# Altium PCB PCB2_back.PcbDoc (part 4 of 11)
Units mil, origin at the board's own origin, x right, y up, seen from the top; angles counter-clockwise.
Board outline 6299 x 3937 mil, 4 copper layers (TopLayer, GROUND, VCC, BottomLayer); 290 components, 470 nets, 2252 pads, 825 vias.
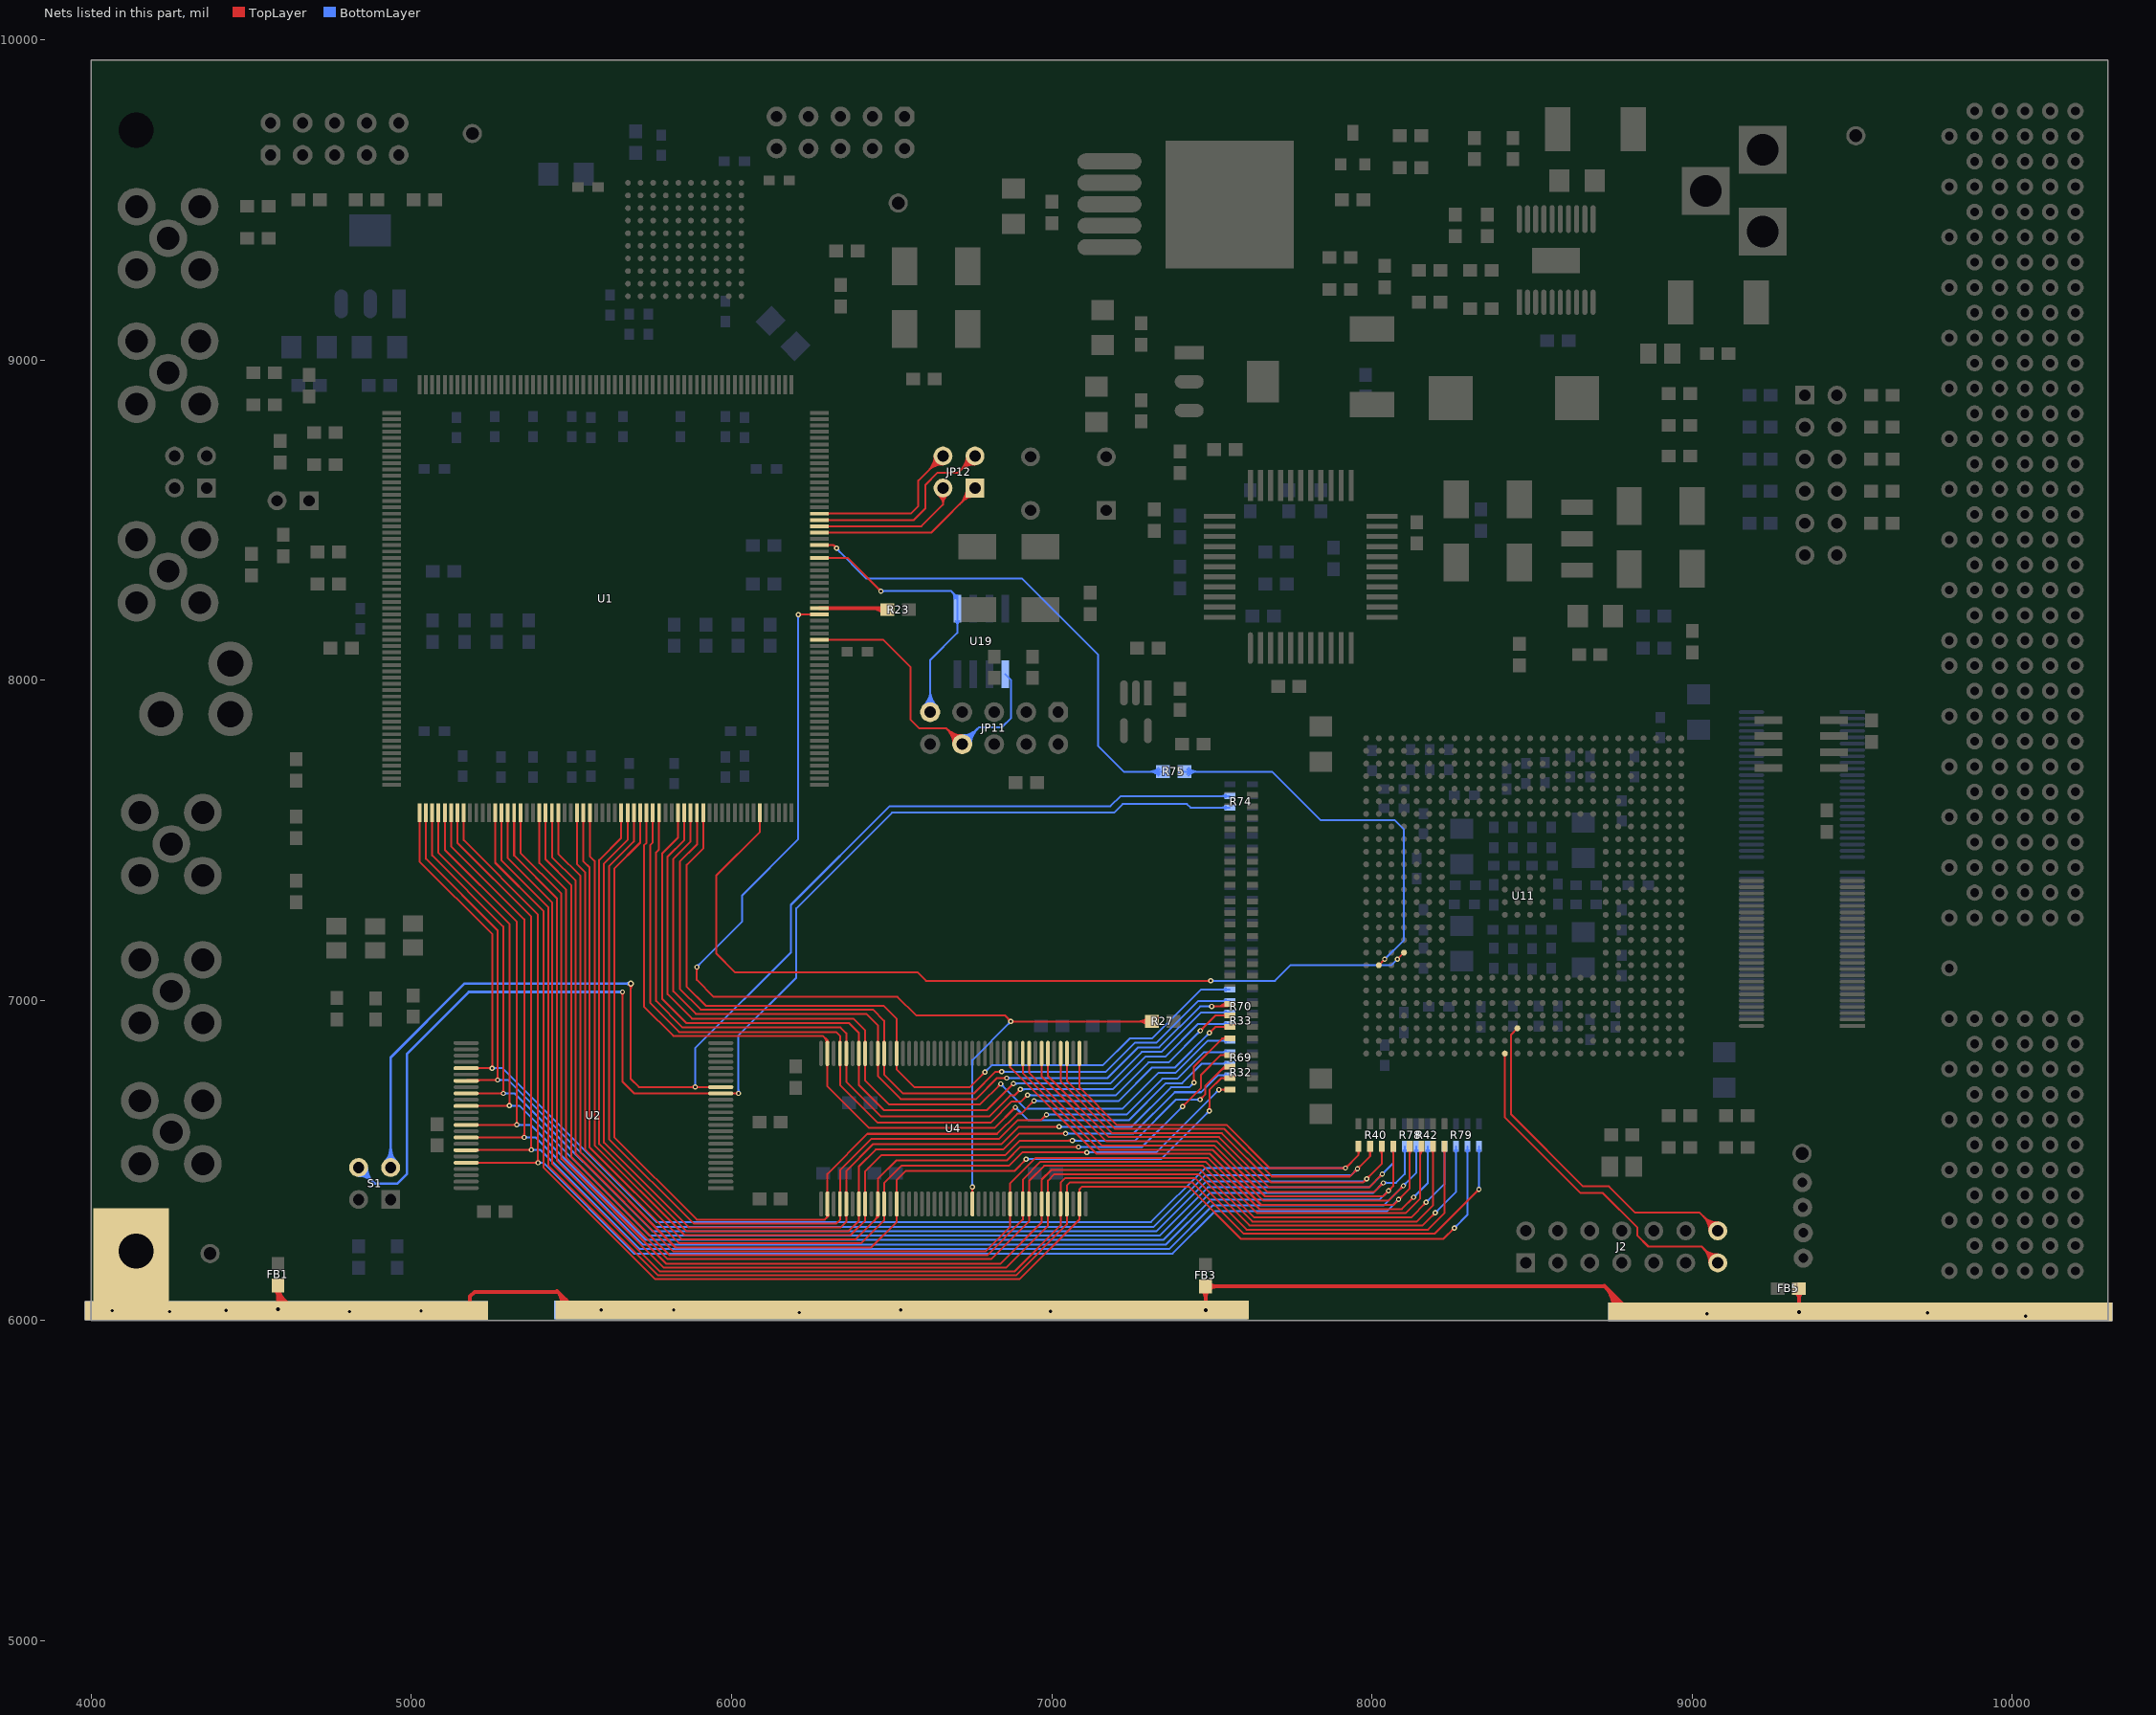
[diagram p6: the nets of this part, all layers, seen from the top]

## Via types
v1: diameter 16, hole 8, TopLayer to BottomLayer, 408 vias
v2: diameter 20, hole 10, TopLayer to BottomLayer, 221 vias
v3: diameter 24, hole 12, TopLayer to BottomLayer, 194 vias
v4: diameter 56.69, hole 56.69, TopLayer to BottomLayer, 2 vias

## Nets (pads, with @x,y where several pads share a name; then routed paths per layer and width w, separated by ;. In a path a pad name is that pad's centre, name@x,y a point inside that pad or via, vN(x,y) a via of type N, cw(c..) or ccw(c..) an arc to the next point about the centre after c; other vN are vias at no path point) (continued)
EA21: R74.7 S1.3 U2.17 | length 4303.4
  TopLayer w6: v2@5680.05,7047.05 cw(c5668.1,7035.1) 5685,7035.1 cw(c5701.9,7035.1) v2@5689.95,7047.05 ; v2(5685,7052) 5685,6754 5710.04,6728.96 U2.17@5966,6728.96 ; v1@5882.5,6725.42 ccw(c5873.97,6716.89) 5873.97,6728.96 ccw(c5873.97,6741.03) v1@5882.5,6732.5 ; v1@5889.58,6725.42 cw(c5898.11,6716.89) 5898.11,6728.96 cw(c5898.11,6741.03) v1@5889.58,6732.5 ; U2.17@5930.48,6726.91 ccw(c5925.52,6721.95) 5925.52,6728.96 ccw(c5925.52,6735.97) U2.17@5930.48,6731.01
  BottomLayer w6: v1@5882.5,6732.5 ccw(c5873.97,6741.03) 5886.04,6741.03 ccw(c5898.11,6741.03) v1@5889.58,6732.5 ; v1(5886.04,6728.96) 5886.04,6851.04 6185,7150 6185,7298 6493,7606 7183,7606 7215,7638 R74.7@7555.84,7638 ; R74.7@7543.1,7633.76 ccw(c7532.86,7623.51) 7532.86,7638 ccw(c7532.86,7652.49) R74.7@7543.1,7642.24
  BottomLayer w8: S1.3@4916.95,6496.05 ccw(c4873.37,6539.63) 4935,6539.63 ccw(c4996.63,6539.63) S1.3@4953.05,6496.05 ; S1.3@4922.61,6490.39 ccw(c4892.68,6520.32) 4935,6520.32 ccw(c4977.32,6520.32) S1.3@4947.39,6490.39 ; S1.3@4923,6490 S1.3@4935,6478 4935,6822 5165,7052 v2(5685,7052) ; v2@5680.76,7047.76 ccw(c5670.51,7037.51) 5670.51,7052 ccw(c5670.51,7066.49) v2@5680.76,7056.24
EA22: R74.6 S1.4 U2.16 | length 4396.5
  TopLayer w6: v1@5655.46,7022.46 cw(c5646.93,7013.93) 5659,7013.93 cw(c5671.07,7013.93) v1@5662.54,7022.46 ; v1(5659,7026) 5659,6746.27 5696,6709.27 ; 5695,6709 5966,6709.23 v1(6021.27,6709.27) ; 5925.34,6709.19 ccw(c5925.33,6716.46) U2.16@5930.48,6711.33 ; 5925.7,6709.19 cw(c5925.71,6702.44) U2.16@5930.48,6707.22 ; U2.16@6001.52,6707.22 cw(c6006.44,6702.31) 6006.43,6709.26 ; U2.16@6001.52,6711.33 ccw(c6006.52,6716.34) 6006.52,6709.26 ; v1@6017.74,6705.74 ccw(c6009.21,6697.19) 6009.2,6709.26 ccw(c6009.19,6721.34) v1@6017.74,6712.81
  BottomLayer w6: v1@6017.74,6712.81 ccw(c6009.2,6721.35) 6021.28,6721.35 ccw(c6033.35,6721.35) v1@6024.81,6712.81 ; v1(6021.27,6709.27) 6021.27,6890.27 6202,7071 6202,7287 6501,7586 7194,7586 7221,7613 7422,7613 7433,7602 R74.6@7555.84,7602 ; R74.6@7543.1,7597.76 ccw(c7532.86,7587.51) 7532.86,7602 ccw(c7532.86,7616.49) R74.6@7543.1,7606.24
  BottomLayer w8: S1.4@4835,6452.47 cw(c4835,6390.84) 4878.58,6434.42 cw(c4922.16,6478) S1.4@4860.53,6478 ; S1.4@4835,6460.47 cw(c4835,6418.16) 4864.92,6448.08 cw(c4894.84,6478) S1.4@4852.53,6478 ; S1.4@4835,6478 4885,6428 4956,6428 4986,6458 4986,6833 5179,7026 v1(5659,7026) ; v1@5656.17,7023.17 ccw(c5649.34,7016.34) 5649.34,7026 ccw(c5649.34,7035.66) v1@5656.17,7028.83
ECLKIN: R75.2 U11.H25 | length 1321.4
  TopLayer w6: U11.H25@8021.12,7109.59 v1(8039.53,7128)
  BottomLayer w6: R75.2@7413.46,7714 7688,7714 7839,7563 8070,7563 8100,7533 8100,7188.47 v1(8039.53,7128) ; R75.2@7422.99,7706.44 cw(c7441.23,7688.2) 7441.23,7714 cw(c7441.23,7739.8) R75.2@7422.99,7721.56 ; R75.2@7427.23,7702.2 cw(c7455.71,7673.72) 7455.71,7714 cw(c7455.71,7754.28) R75.2@7427.23,7725.8
ECLKOUT1: R27.2 U1.28 U4.68 | length 3730.1
  TopLayer w6: v1@5887.46,7100.46 cw(c5878.93,7091.93) 5891,7091.93 cw(c5903.07,7091.93) v1@5894.54,7100.46 ; v1(5891,7104) 5891,7064 5944,7011 6518,7011 6576,6953 6853,6953 v1(6872,6934) R27.2@7312.54,6934 ; v1(6208,8204.79) U1.28@6274.31,8204.79 ; v1@6211.54,8201.25 cw(c6220.07,8192.72) 6220.07,8204.79 cw(c6220.07,8216.86) v1@6211.54,8208.32 ; U1.28@6248.63,8202.73 ccw(c6243.67,8197.77) 6243.67,8204.79 ccw(c6243.67,8211.8) U1.28@6248.63,8206.84 ; v1@6748.13,6413.13 cw(c6739.6,6404.6) 6751.67,6404.6 cw(c6763.74,6404.6) v1@6755.21,6413.13 ; U4.68@6749.62,6399.52 ccw(c6744.66,6404.48) 6751.67,6404.48 ccw(c6758.68,6404.48) U4.68@6753.72,6399.52 ; U4.68@6751.67,6364 v1(6751.67,6416.67) ; v1@6867,6934 ccw(c6854.93,6934) 6863.46,6942.54 ccw(c6872,6951.07) v1@6872,6939 ; v1@6875.54,6930.46 cw(c6884.07,6921.93) 6884.07,6934 cw(c6884.07,6946.07) v1@6875.54,6937.54 ; R27.2@7298.77,6922.2 ccw(c7270.29,6893.72) 7270.29,6934 ccw(c7270.29,6974.28) R27.2@7298.77,6945.8 ; R27.2@7303.01,6926.44 ccw(c7284.77,6908.2) 7284.77,6934 ccw(c7284.77,6959.8) R27.2@7303.01,6941.56
  BottomLayer w6: v1(5891,7104) 6033,7246 6033,7328 6208,7503 v1(6208,8204.79) ; v1@5891,7109 ccw(c5891,7121.07) 5899.54,7112.54 ccw(c5908.07,7104) v1@5896,7104 ; v1@6204.46,8201.25 cw(c6195.93,8192.72) 6208,8192.72 cw(c6220.07,8192.72) v1@6211.54,8201.25 ; v1@6748.13,6420.21 ccw(c6739.6,6428.74) 6751.67,6428.74 ccw(c6763.74,6428.74) v1@6755.21,6420.21 ; v1(6751.67,6416.67) 6751.67,6813.67 v1(6872,6934) ; v1@6867,6934 cw(c6854.93,6934) 6863.46,6925.46 cw(c6872,6916.93) v1@6872,6929
ECLKOUT2: U1.235 U11.J23 | length 2764.6
  TopLayer w6: U1.235@6086.23,7560.02 cw(c6081.27,7555.06) 6088.28,7555.06 cw(c6095.3,7555.06) U1.235@6090.34,7560.02 ; U1.235@6088.28,7585.69 6088.28,7526.28 5952,7390 5952,7146 6010,7088 6580,7088 6607,7061 v1(7496,7061) ; v1@7492.46,7057.46 ccw(c7483.93,7048.93) 7483.93,7061 ccw(c7483.93,7073.07) v1@7492.46,7064.54 ; v1(8078.9,7128) U11.J23@8099.86,7148.96
  BottomLayer w6: v1(7496,7061) 7697,7061 7746,7110 8060.9,7110 v1(8078.9,7128) ; v1@7499.54,7057.46 cw(c7508.07,7048.93) 7508.07,7061 cw(c7508.07,7073.07) v1@7499.54,7064.54
ED00: R40.5 U1.181 U2.29 U4.2 | length 5201.9
  TopLayer w6: U1.181@5023.24,7560.02 cw(c5018.28,7555.06) 5025.29,7555.06 cw(c5032.31,7555.06) U1.181@5027.35,7560.02 ; U1.181@5025.29,7585.69 5025.29,7433.71 5252,7207 v1(5252,6788) U2.29@5170.72,6788.02 ; U2.29@5206.24,6785.96 cw(c5211.19,6781.01) 5211.19,6788.01 cw(c5211.22,6795.04) U2.29@5206.24,6790.07 ; v1@5248.46,6784.47 ccw(c5239.93,6775.93) 5239.93,6788 ccw(c5239.93,6800.07) 5248.47,6791.54 ccw(c5239.93,6800.07) 5252,6800.07 ccw(c5264.07,6800.07) v1@5255.54,6791.54 ; U4.2@7084.26,6798.48 cw(c7079.3,6793.52) 7086.32,6793.52 cw(c7093.33,6793.52) U4.2@7088.37,6798.48 ; U4.2@7086.31,6834 7086.31,6727.69 7204,6610 7547,6610 7681,6476 v1(7917,6476) 7958,6517 R40.5@7958,6543.84 ; v1@7913.46,6472.46 ccw(c7904.93,6463.93) 7904.93,6476 ccw(c7904.93,6488.07) v1@7913.46,6479.54 ; v1@7917,6481 ccw(c7917,6493.07) 7925.54,6484.54 ccw(c7934.07,6476) v1@7922,6476 ; R40.5@7953.76,6531.1 cw(c7943.51,6520.86) 7958,6520.86 cw(c7972.49,6520.86) R40.5@7962.24,6531.1
  BottomLayer w6: v1(5252,6788) 5284.98,6788.02 5765,6308 7310,6308 7478,6476 v1(7917,6476) ; v1@5255.54,6784.47 cw(c5264.08,6775.93) 5264.07,6788.01 cw(c5264.07,6800.08) v1@5255.53,6791.54 ; v1@7913.46,6472.46 ccw(c7904.93,6463.93) 7904.93,6476 ccw(c7904.93,6488.07) v1@7913.46,6479.54
ED01: R40.6 U1.182 U2.31 U4.4 | length 5358.9
  TopLayer w6: U1.182@5042.92,7560.02 cw(c5037.96,7555.06) 5044.98,7555.06 cw(c5051.99,7555.06) U1.182@5047.03,7560.02 ; U1.182@5044.98,7585.69 5044.98,7442.02 5269,7218 v1(5269,6751) U2.31@5173.08,6751 ; U2.31@5170.72,6748.65 U2.31@5173.08,6748.65 ; U2.31@5206.24,6746.59 cw(c5216.89,6735.94) 5216.89,6751 ; v1@5265.46,6747.46 ccw(c5256.93,6738.93) 5256.93,6751 ccw(c5256.93,6763.07) 5265.46,6754.54 ccw(c5256.93,6763.07) 5269,6763.07 ccw(c5281.07,6763.07) v1@5272.54,6754.54 ; U4.4@7044.89,6798.48 cw(c7039.93,6793.52) 7046.95,6793.52 cw(c7053.96,6793.52) U4.4@7049,6798.48 ; U4.4@7046.94,6834 7046.94,6749.06 7198,6598 7539,6598 7687,6450 7931,6450 7994,6513 R40.6@7994,6543.84 ; v1@7949.5,6473.5 cw(c7937.43,6473.5) 7945.97,6464.97 cw(c7954.5,6456.43) v1@7954.5,6468.5 ; v1@7954.5,6478.5 ccw(c7954.5,6490.57) 7963.04,6482.04 ccw(c7971.57,6473.5) v1@7959.5,6473.5 ; R40.6@7989.76,6531.1 cw(c7979.51,6520.86) 7994,6520.86 cw(c8008.49,6520.86) R40.6@7998.24,6531.1
  BottomLayer w6: v1(5269,6751) 5303,6751 5761,6293 7318,6293 7478,6453 7934,6453 v1(7954.5,6473.5) ; v1@5272.54,6747.46 cw(c5281.07,6738.93) 5281.07,6751 cw(c5281.07,6763.07) v1@5272.54,6754.54 ; v1@7949.5,6473.5 cw(c7937.43,6473.5) 7945.97,6464.97 cw(c7954.5,6456.43) v1@7954.5,6468.5
ED02: R40.7 U1.183 U2.33 U4.5 | length 5494.4
  TopLayer w6: U1.183@5062.61,7560.02 cw(c5057.65,7555.06) 5064.66,7555.06 cw(c5071.68,7555.06) U1.183@5066.72,7560.02 ; U1.183@5064.66,7585.69 5064.66,7452.34 5286.73,7230.27 v1(5286.73,6709.27) U2.33@5170.72,6709.27 ; U2.33@5206.24,6707.22 cw(c5211.2,6702.26) 5211.2,6709.28 cw(c5211.2,6716.29) U2.33@5206.24,6711.33 ; v1@5283.19,6705.74 ccw(c5274.65,6697.2) 5274.65,6709.28 ccw(c5274.65,6721.35) 5283.19,6712.81 ccw(c5274.65,6721.35) 5286.73,6721.35 ccw(c5298.8,6721.35) v1@5290.26,6712.81 ; U4.5@7025.21,6798.48 cw(c7020.25,6793.52) 7027.26,6793.52 cw(c7034.27,6793.52) U4.5@7029.31,6798.48 ; U4.5@7027.26,6834 7027.26,6746.74 7188.95,6585.05 7530.95,6585.05 7684,6432 7973,6432 8030,6489 R40.7@8030,6543.84 ; v1@7979,6443 cw(c7966.93,6443) 7975.46,6434.46 cw(c7984,6425.93) v1@7984,6438 ; v1@7984,6448 ccw(c7984,6460.07) 7992.54,6451.54 ccw(c8001.07,6443) v1@7989,6443 ; R40.7@8025.76,6531.1 cw(c8015.51,6520.86) 8030,6520.86 cw(c8044.49,6520.86) R40.7@8034.24,6531.1
  BottomLayer w6: v1(5286.73,6709.27) 5321.73,6709.27 5752,6279 7327,6279 7483,6435 7976,6435 ; v1@5290.26,6705.74 cw(c5298.8,6697.2) 5298.8,6709.28 cw(c5298.8,6721.35) v1@5290.26,6712.81 ; v1@7979.01,6442.77 cw(c7968.72,6442.28) 7976,6435 ; v1@7983.77,6438.01 ccw(c7983.28,6427.72) 7976,6435 ; v1(7984,6443) 7976,6435
ED03: R78.8 U1.184 U2.35 U4.7 | length 5659.6
  TopLayer w6: U1.184@5082.29,7560.02 cw(c5077.33,7555.06) 5084.35,7555.06 cw(c5091.36,7555.06) U1.184@5086.4,7560.02 ; U1.184@5084.35,7585.69 5084.35,7460.65 5306,7239 v1(5306,6671) 5171.82,6671 U2.35@5170.72,6669.9 ; U2.35@5206.24,6667.85 cw(c5213.85,6660.25) 5213.85,6671 ; v1@5302.46,6667.46 ccw(c5293.93,6658.93) 5293.93,6671 ccw(c5293.93,6683.07) 5302.46,6674.54 ccw(c5293.93,6683.07) 5306,6683.07 ccw(c5318.07,6683.07) v1@5309.54,6674.54 ; U4.7@6985.84,6798.48 cw(c6980.88,6793.52) 6987.89,6793.52 cw(c6994.9,6793.52) U4.7@6989.94,6798.48 ; U4.7@6987.89,6834 6987.89,6763.11 7178.14,6572.86 7522.14,6572.86 7679,6416 7991,6416 v1(8032,6457) ; v1@8027,6457 cw(c8014.93,6457) 8023.46,6448.46 cw(c8032,6439.93) v1@8032,6452
  BottomLayer w6: v1(5306,6671) 5337,6671 5743,6265 7336,6265 7487,6416 7991,6416 8066,6491 R78.8@8066,6543.84 ; v1@5309.54,6667.46 cw(c5318.07,6658.93) 5318.07,6671 cw(c5318.07,6683.07) v1@5309.54,6674.54 ; v1@8027,6457 cw(c8014.93,6457) 8023.46,6448.46 cw(c8032,6439.93) v1@8032,6452 ; v1@8032,6462 ccw(c8032,6474.07) 8040.54,6465.54 ccw(c8049.07,6457) v1@8037,6457 ; R78.8@8061.76,6531.1 cw(c8051.51,6520.86) 8066,6520.86 cw(c8080.49,6520.86) R78.8@8070.24,6531.1
ED04: R78.7 U1.185 U2.38 U4.8 | length 5788.8
  TopLayer w6: U1.185@5101.98,7560.02 cw(c5097.02,7555.06) 5104.03,7555.06 cw(c5111.05,7555.06) U1.185@5106.09,7560.02 ; U1.185@5104.03,7585.69 5104.03,7469.97 5329,7245 v1(5329,6611) U2.38@5170.72,6610.85 ; U2.38@5206.25,6608.8 cw(c5211.29,6603.77) 5211.28,6610.89 ; U2.38@5206.24,6612.91 ccw(c5211.12,6617.79) 5211.13,6610.89 ; v1@5325.47,6607.46 ccw(c5316.94,6598.92) 5316.93,6610.99 ccw(c5316.92,6623.06) 5325.46,6614.53 ccw(c5316.93,6623.07) 5329,6623.07 ccw(c5341.07,6623.07) v1@5332.54,6614.54 ; U4.8@6966.15,6798.48 cw(c6961.19,6793.52) 6968.2,6793.52 cw(c6975.22,6793.52) U4.8@6970.26,6798.48 ; U4.8@6968.2,6834 6968.2,6761.8 7170.75,6559.25 7515.75,6559.25 7673,6402 8007,6402 v1(8035,6430) ; v1@8030,6430 cw(c8017.93,6430) 8026.46,6421.46 cw(c8035,6412.93) v1@8035,6425
  BottomLayer w6: v1(5329,6611) 5372.15,6610.85 5731,6252 7348,6252 7494,6398 8003,6398 v1(8035,6430) 8075,6430 8102,6457 R78.7@8102,6543.84 ; v1@5332.52,6607.45 cw(c5341.03,6598.89) 5341.07,6610.96 cw(c5341.11,6623.03) v1@5332.55,6614.52 ; v1@8030,6430 cw(c8017.93,6430) 8026.46,6421.46 cw(c8035,6412.93) v1@8035,6425 ; v1@8038.54,6426.46 cw(c8047.07,6417.93) 8047.07,6430 cw(c8047.07,6442.07) v1@8038.54,6433.54 ; R78.7@8097.76,6531.1 cw(c8087.51,6520.86) 8102,6520.86 cw(c8116.49,6520.86) R78.7@8106.24,6531.1
ED05: R40.8 U1.186 U2.40 U4.10 | length 5857.2
  TopLayer w6: U1.186@5121.66,7560.02 cw(c5116.7,7555.06) 5123.72,7555.06 cw(c5130.73,7555.06) U1.186@5125.77,7560.02 ; U1.186@5123.72,7585.69 5123.72,7481.28 5352,7253 v1(5352,6572) 5171.24,6572 U2.40@5170.72,6571.48 ; U2.40@5206.24,6569.43 cw(c5212.46,6563.21) 5212.46,6572 ; v1@5348.46,6568.46 ccw(c5339.93,6559.93) 5339.93,6572 ccw(c5339.93,6584.07) 5348.46,6575.54 ccw(c5339.93,6584.07) 5352,6584.07 ccw(c5364.07,6584.07) v1@5355.54,6575.54 ; U4.10@6926.78,6798.48 cw(c6921.82,6793.52) 6928.84,6793.52 cw(c6935.85,6793.52) U4.10@6930.89,6798.48 ; U4.10@6928.84,6834 6928.84,6774.16 7157,6546 7508,6546 7666,6388 8034,6388 8066,6420 R40.8@8066,6543.84 ; v1@8046.45,6405.45 cw(c8034.38,6405.45) 8042.92,6396.92 cw(c8051.45,6388.38) v1@8051.45,6400.45 ; v1@8051.45,6410.45 ccw(c8051.45,6422.53) 8059.99,6413.99 ccw(c8068.53,6405.45) v1@8056.45,6405.45 ; R40.8@8061.76,6531.1 cw(c8051.51,6520.86) 8066,6520.86 cw(c8080.49,6520.86) R40.8@8070.24,6531.1
  BottomLayer w6: v1(5352,6572) 5387,6572 5722,6237 7356,6237 7496,6377 8023,6377 v1(8051.45,6405.45) ; v1@5355.54,6568.46 cw(c5364.07,6559.93) 5364.07,6572 cw(c5364.07,6584.07) v1@5355.54,6575.54 ; v1@8046.45,6405.45 cw(c8034.38,6405.45) 8042.92,6396.92 cw(c8051.45,6388.38) v1@8051.45,6400.45
ED06: R78.6 U1.187 U2.42 U4.11 | length 6026.8
  TopLayer w6: U1.187@5141.35,7560.02 cw(c5136.39,7555.06) 5143.4,7555.06 cw(c5150.42,7555.06) U1.187@5145.46,7560.02 ; U1.187@5143.4,7585.69 5143.4,7491.6 5374,7261 v1(5374,6533) 5171.61,6533 U2.42@5170.72,6532.11 ; U2.42@5206.24,6530.06 cw(c5213.35,6522.95) 5213.35,6533 ; v1@5370.46,6529.46 ccw(c5361.93,6520.93) 5361.93,6533 ccw(c5361.93,6545.07) 5370.46,6536.54 ccw(c5361.93,6545.07) 5374,6545.07 ccw(c5386.07,6545.07) v1@5377.54,6536.54 ; U4.11@6907.1,6798.48 cw(c6902.14,6793.52) 6909.15,6793.52 cw(c6916.16,6793.52) U4.11@6911.2,6798.48 ; U4.11@6909.15,6834 6909.15,6772.85 7148.53,6533.47 7501.53,6533.47 7661,6374 8051,6374 v1(8098,6421) ; v1@8093,6421 cw(c8080.93,6421) 8089.46,6412.46 cw(c8098,6403.93) v1@8098,6416
  BottomLayer w6: v1(5374,6533) 5403,6533 5713,6223 7366,6223 7503,6360 8037,6360 8138,6461 R78.6@8138,6543.84 ; v1@5377.54,6529.46 cw(c5386.07,6520.93) 5386.07,6533 cw(c5386.07,6545.07) v1@5377.54,6536.54 ; v1@8093,6421 cw(c8080.93,6421) 8089.46,6412.46 cw(c8098,6403.93) v1@8098,6416 ; v1@8098,6426 ccw(c8098,6438.07) 8106.54,6429.54 ccw(c8115.07,6421) v1@8103,6421 ; R78.6@8133.76,6531.1 cw(c8123.51,6520.86) 8138,6520.86 cw(c8152.49,6520.86) R78.6@8142.24,6531.1
ED07: R42.5 U1.188 U2.44 U4.13 | length 6081.2
  TopLayer w6: U1.188@5161.03,7560.02 cw(c5156.07,7555.06) 5163.09,7555.06 cw(c5170.1,7555.06) U1.188@5165.14,7560.02 ; U1.188@5163.09,7585.69 5163.09,7499.91 5395,7268 v1(5395,6492.74) U2.44@5170.72,6492.74 ; U2.44@5206.24,6490.69 cw(c5211.2,6485.73) 5211.2,6492.74 cw(c5211.2,6499.75) U2.44@5206.24,6494.79 ; v1@5391.46,6489.2 ccw(c5382.93,6480.67) 5382.93,6492.74 ccw(c5382.93,6504.81) 5391.46,6496.28 ccw(c5382.93,6504.81) 5395,6504.81 ccw(c5407.07,6504.81) v1@5398.54,6496.28 ; U4.13@6867.73,6798.48 cw(c6862.77,6793.52) 6869.78,6793.52 cw(c6876.79,6793.52) U4.13@6871.83,6798.48 ; U4.13@6869.78,6834 6869.78,6790.22 7139,6521 7494,6521 7654,6361 8067,6361 8118,6412 R42.5@8118,6543.84 ; 8073.76,6367.76 ccw(c8063.51,6378) v1@8078,6378 ; 8076.17,6370.17 cw(c8083,6363.34) v1@8083,6373 ; v1@8083,6383 ccw(c8083,6397.49) 8093.24,6387.24 ; v1@8088,6378 cw(c8097.66,6378) 8090.83,6384.83 ; R42.5@8113.76,6531.1 cw(c8103.51,6520.86) 8118,6520.86 cw(c8132.49,6520.86) R42.5@8122.24,6531.1
  BottomLayer w6: v1(5395,6492.74) 5411.26,6492.74 5695,6209 7377,6209 7509,6341 8046,6341 v1(8083,6378) ; v1@5398.54,6489.2 cw(c5407.07,6480.67) 5407.07,6492.74 cw(c5407.07,6504.81) v1@5398.54,6496.28 ; v1@8078,6378 cw(c8065.93,6378) 8074.46,6369.46 cw(c8083,6360.93) v1@8083,6373
ED08: R78.5 U1.202 U4.74 | length 4391.8
  TopLayer w6: U1.202@5436.62,7560.02 cw(c5431.66,7555.06) 5438.68,7555.06 cw(c5445.69,7555.06) U1.202@5440.73,7560.02 ; U1.202@5438.68,7585.69 5438.68,7447.32 5513,7373 5513,6521 5818,6216 6793,6216 6869.78,6292.78 6869.78,6428.78 6949,6508 7488,6508 7648,6348 8093,6348 v1(8130,6385) ; U4.74@6867.73,6328.48 cw(c6862.77,6323.52) 6869.78,6323.52 cw(c6876.79,6323.52) U4.74@6871.83,6328.48 ; U4.74@6867.73,6399.52 ccw(c6862.77,6404.48) 6869.78,6404.48 ccw(c6876.79,6404.48) U4.74@6871.83,6399.52 ; v1@8125,6385 cw(c8112.93,6385) 8121.46,6376.46 cw(c8130,6367.93) v1@8130,6380
  BottomLayer w6: v1(8130,6385) 8174,6429 R78.5@8174,6543.84 ; v1@8130,6390 ccw(c8130,6402.07) 8138.54,6393.54 ccw(c8147.07,6385) v1@8135,6385 ; R78.5@8169.76,6531.1 cw(c8159.51,6520.86) 8174,6520.86 cw(c8188.49,6520.86) R78.5@8178.24,6531.1
ED09: R42.6 U1.201 U4.76 | length 4396.3
  TopLayer w6: U1.201@5416.94,7560.02 cw(c5411.98,7555.06) 5418.99,7555.06 cw(c5426.01,7555.06) U1.201@5421.05,7560.02 ; U1.201@5418.99,7585.69 5418.99,7440.01 5499,7360 5499,6512 5807,6204 6798,6204 6909.15,6315.15 6909.15,6440.15 6965,6496 7480,6496 7641,6335 8105,6335 8150,6380 8150,6539.84 R42.6@8154,6543.84 ; U4.76@6907.1,6328.48 cw(c6902.14,6323.52) 6909.15,6323.52 cw(c6916.16,6323.52) U4.76@6911.2,6328.48 ; U4.76@6907.1,6399.52 ccw(c6902.14,6404.48) 6909.15,6404.48 ccw(c6916.16,6404.48) U4.76@6911.2,6399.52 ; 8150,6511.2 cw(c8178.14,6511.2) R42.6@8158.24,6531.1 ; 8150,6525.69 cw(c8163.66,6525.69) R42.6@8154,6535.34
ED10: R79.8 U1.200 U4.77 | length 4501.4
  TopLayer w6: U1.200@5397.25,7560.02 cw(c5392.29,7555.06) 5399.31,7555.06 cw(c5406.32,7555.06) U1.200@5401.36,7560.02 ; U1.200@5399.31,7585.69 5399.31,7428.69 5482,7346 5482,6510 5800,6192 6811,6192 6928.84,6309.84 6928.84,6435.84 6976,6483 7472,6483 7633,6322 8122,6322 v1(8169,6369) ; U4.77@6926.78,6328.48 cw(c6921.82,6323.52) 6928.84,6323.52 cw(c6935.85,6323.52) U4.77@6930.89,6328.48 ; U4.77@6926.78,6399.52 ccw(c6921.82,6404.48) 6928.84,6404.48 ccw(c6935.85,6404.48) U4.77@6930.89,6399.52 ; v1@8164,6369 cw(c8151.93,6369) 8160.46,6360.46 cw(c8169,6351.93) v1@8169,6364
  BottomLayer w6: v1(8169,6369) 8226,6426 R79.8@8226,6543.84 ; v1@8169,6374 ccw(c8169,6386.07) 8177.54,6377.54 ccw(c8186.07,6369) v1@8174,6369 ; R79.8@8221.76,6531.1 cw(c8211.51,6520.86) 8226,6520.86 cw(c8240.49,6520.86) R79.8@8230.24,6531.1
ED11: R42.7 U1.197 U4.79 | length 4518.7
  TopLayer w6: U1.197@5338.2,7560.02 cw(c5333.24,7555.06) 5340.25,7555.06 cw(c5347.27,7555.06) U1.197@5342.31,7560.02 ; U1.197@5340.25,7585.69 5340.25,7460.75 5468,7333 5468,6505 5795,6178 6840.2,6178 6968.2,6306 6968.2,6440.2 6998,6470 7465,6470 7626,6309 8140,6309 8190,6359 R42.7@8190,6543.84 ; U4.79@6966.15,6328.48 cw(c6961.19,6323.52) 6968.2,6323.52 cw(c6975.22,6323.52) U4.79@6970.26,6328.48 ; U4.79@6966.15,6399.52 ccw(c6961.19,6404.48) 6968.2,6404.48 ccw(c6975.22,6404.48) U4.79@6970.26,6399.52 ; R42.7@8185.76,6531.1 cw(c8175.51,6520.86) 8190,6520.86 cw(c8204.49,6520.86) R42.7@8194.24,6531.1
ED12: R79.7 U1.196 U4.80 | length 4637.8
  TopLayer w6: U1.196@5318.51,7560.02 cw(c5313.55,7555.06) 5320.57,7555.06 cw(c5327.58,7555.06) U1.196@5322.62,7560.02 ; U1.196@5320.57,7585.69 5320.57,7452.43 5454,7319 5454,6499 5788,6165 6857,6165 6987.89,6295.89 6987.89,6436.89 7008,6457 7457,6457 7617,6297 8158,6297 v1(8197,6336) ; U4.80@6985.84,6328.48 cw(c6980.88,6323.52) 6987.89,6323.52 cw(c6994.9,6323.52) U4.80@6989.94,6328.48 ; U4.80@6985.84,6399.52 ccw(c6980.88,6404.48) 6987.89,6404.48 ccw(c6994.9,6404.48) U4.80@6989.94,6399.52 ; v1@8192,6336 cw(c8179.93,6336) 8188.46,6327.46 cw(c8197,6318.93) v1@8197,6331
  BottomLayer w6: v1(8197,6336) 8262,6401 R79.7@8262,6543.84 ; v1@8197,6341 ccw(c8197,6353.07) 8205.54,6344.54 ccw(c8214.07,6336) v1@8202,6336 ; R79.7@8257.76,6531.1 cw(c8247.51,6520.86) 8262,6520.86 cw(c8276.49,6520.86) R79.7@8266.24,6531.1
ED13: R42.8 U1.195 U4.82 | length 4630.8
  TopLayer w6: U1.195@5298.83,7560.02 cw(c5293.87,7555.06) 5300.88,7555.06 cw(c5307.9,7555.06) U1.195@5302.94,7560.02 ; U1.195@5300.88,7585.69 5300.88,7444.12 5440,7305 5440,6489 5776,6153 6883,6153 7027.26,6297.26 7027.26,6430.26 7042,6445 7447,6445 7608,6284 8175,6284 8226,6335 R42.8@8226,6543.84 ; U4.82@7025.21,6328.48 cw(c7020.25,6323.52) 7027.26,6323.52 cw(c7034.27,6323.52) U4.82@7029.31,6328.48 ; U4.82@7025.21,6399.52 ccw(c7020.25,6404.48) 7027.26,6404.48 ccw(c7034.27,6404.48) U4.82@7029.31,6399.52 ; R42.8@8221.76,6531.1 cw(c8211.51,6520.86) 8226,6520.86 cw(c8240.49,6520.86) R42.8@8230.24,6531.1
ED14: R79.5 U1.194 U4.83 | length 4753.6
  TopLayer w6: U1.194@5279.14,7560.02 cw(c5274.18,7555.06) 5281.2,7555.06 cw(c5288.21,7555.06) U1.194@5283.25,7560.02 ; U1.194@5281.2,7585.69 5281.2,7436.8 5427,7291 5427,6485 5771,6141 6888,6141 7046.94,6299.94 7046.94,6421.94 7056,6431 7440,6431 7600,6271 8195,6271 v1(8334,6410) ; U4.83@7044.89,6328.48 cw(c7039.93,6323.52) 7046.95,6323.52 cw(c7053.96,6323.52) U4.83@7049,6328.48 ; U4.83@7044.89,6399.52 ccw(c7039.93,6404.48) 7046.95,6404.48 ccw(c7053.96,6404.48) U4.83@7049,6399.52 ; v1@8329,6410 cw(c8316.93,6410) 8325.46,6401.46 cw(c8334,6392.93) v1@8334,6405
  BottomLayer w6: R79.5@8329.76,6531.1 cw(c8319.51,6520.86) 8334,6520.86 cw(c8348.49,6520.86) R79.5@8338.24,6531.1 ; v1@8330.46,6413.54 ccw(c8321.93,6422.07) 8334,6422.07 ccw(c8346.07,6422.07) v1@8337.54,6413.54 ; v1(8334,6410) R79.5@8334,6543.84
ED15: R79.6 U1.193 U4.85 | length 4781.5
  TopLayer w6: U1.193@5259.46,7560.02 cw(c5254.5,7555.06) 5261.51,7555.06 cw(c5268.53,7555.06) U1.193@5263.57,7560.02 ; U1.193@5261.51,7585.69 5261.51,7429.49 5413,7278 5413,6477 5761,6129 6899,6129 7086.31,6316.31 7086.31,6410.31 7094,6418 7428,6418 7591,6255 8223,6255 v1(8257,6289) ; U4.85@7084.26,6328.48 cw(c7079.3,6323.52) 7086.32,6323.52 cw(c7093.33,6323.52) U4.85@7088.37,6328.48 ; U4.85@7084.26,6399.52 ccw(c7079.3,6404.48) 7086.32,6404.48 ccw(c7093.33,6404.48) U4.85@7088.37,6399.52 ; v1@8252,6289 cw(c8239.93,6289) 8248.46,6280.46 cw(c8257,6271.93) v1@8257,6284
  BottomLayer w6: v1(8257,6289) 8298,6330 R79.6@8298,6543.84 ; v1@8257,6294 ccw(c8257,6306.07) 8265.54,6297.54 ccw(c8274.07,6289) v1@8262,6289 ; R79.6@8293.76,6531.1 cw(c8283.51,6520.86) 8298,6520.86 cw(c8312.49,6520.86) R79.6@8302.24,6531.1
ED16: R70.8 U1.226 U4.31 | length 2703.8
  TopLayer w6: U1.226@5909.06,7560.02 cw(c5904.1,7555.06) 5911.12,7555.06 cw(c5918.13,7555.06) U1.226@5913.17,7560.02 ; U1.226@5911.12,7585.69 5911.12,7474.12 5860,7423 5860,7042 5919,6983 6474,6983 6515.45,6941.55 6515.45,6783.55 6571,6728 6743,6728 v1(6791,6776) ; U4.31@6513.4,6798.48 cw(c6508.44,6793.52) 6515.45,6793.52 cw(c6522.46,6793.52) U4.31@6517.5,6798.48 ; U4.31@6513.4,6869.52 ccw(c6508.44,6874.48) 6515.45,6874.48 ccw(c6522.46,6874.48) U4.31@6517.5,6869.52 ; v1@6786,6776 cw(c6773.93,6776) 6782.46,6767.46 cw(c6791,6758.93) v1@6791,6771
  BottomLayer w6: v1(6791,6776) 6812,6797 7159,6797 7243,6881 7313,6881 7466,7034 R70.8@7555.84,7034 ; v1@6791,6781 ccw(c6791,6793.07) 6799.54,6784.54 ccw(c6808.07,6776) v1@6796,6776 ; R70.8@7543.1,7029.76 ccw(c7532.86,7019.51) 7532.86,7034 ccw(c7532.86,7048.49) R70.8@7543.1,7038.24
ED17: R70.7 U1.225 U4.33 | length 2737
  TopLayer w6: U1.225@5889.38,7560.02 cw(c5884.42,7555.06) 5891.43,7555.06 cw(c5898.45,7555.06) U1.225@5893.49,7560.02 ; U1.225@5891.43,7585.69 5891.43,7486.43 5838,7433 5838,7036 5903,6971 6441,6971 6476.08,6935.92 6476.08,6767.92 6535,6709 6756,6709 6824,6777 v1(6843,6777) ; U4.33@6474.03,6798.48 cw(c6469.07,6793.52) 6476.08,6793.52 cw(c6483.09,6793.52) U4.33@6478.13,6798.48 ; U4.33@6474.03,6869.52 ccw(c6469.07,6874.48) 6476.08,6874.48 ccw(c6483.09,6874.48) U4.33@6478.13,6869.52 ; v1@6839.46,6773.46 ccw(c6830.93,6764.93) 6830.93,6777 ccw(c6830.93,6789.07) v1@6839.46,6780.54
  BottomLayer w6: v1(6843,6777) 7169,6777 7259,6867 7326,6867 7457,6998 R70.7@7555.84,6998 ; v1@6846.54,6773.46 cw(c6855.07,6764.93) 6855.07,6777 cw(c6855.07,6789.07) v1@6846.54,6780.54 ; R70.7@7543.1,6993.76 ccw(c7532.86,6983.51) 7532.86,6998 ccw(c7532.86,7012.49) R70.7@7543.1,7002.24
ED18: R33.5 U1.224 U4.34 | length 2845.8
  TopLayer w6: U1.224@5869.69,7560.02 cw(c5864.73,7555.06) 5871.75,7555.06 cw(c5878.76,7555.06) U1.224@5873.8,7560.02 ; U1.224@5871.75,7585.69 5871.75,7495.75 5818,7442 5818,7028 5888,6958 6420,6958 6456.4,6921.6 6456.4,6763.6 6528,6692 6764,6692 6829,6757 v1(6859,6757) ; U4.34@6454.34,6798.48 cw(c6449.38,6793.52) 6456.4,6793.52 cw(c6463.41,6793.52) U4.34@6458.45,6798.48 ; U4.34@6454.34,6869.52 ccw(c6449.38,6874.48) 6456.4,6874.48 ccw(c6463.41,6874.48) U4.34@6458.45,6869.52 ; v1@6855.46,6753.46 ccw(c6846.93,6744.93) 6846.93,6757 ccw(c6846.93,6769.07) v1@6855.46,6760.54 ; v1(7499,6981) 7547.84,6981 R33.5@7555.84,6989 ; v1@7502.54,6977.46 cw(c7511.07,6968.93) 7511.07,6981 cw(c7511.07,6993.07) v1@7502.54,6984.54 ; 7513.54,6981 ccw(c7513.54,7022.8) R33.5@7543.1,6993.24 ; 7528.03,6981 ccw(c7528.03,7008.31) R33.5@7547.34,6989 ; R33.5@7542.51,6981 ccw(c7542.51,6993.83) R33.5@7551.59,6984.76
  BottomLayer w6: v1(6859,6757) 7174,6757 7270,6853 7335,6853 7463,6981 v1(7499,6981) ; v1@6862.54,6753.46 cw(c6871.07,6744.93) 6871.07,6757 cw(c6871.07,6769.07) v1@6862.54,6760.54 ; v1@7495.46,6977.46 ccw(c7486.93,6968.93) 7486.93,6981 ccw(c7486.93,6993.07) v1@7495.46,6984.54
ED19: R69.8 U1.223 U4.36 | length 2818.5
  TopLayer w6: U1.223@5850.01,7560.02 cw(c5845.05,7555.06) 5852.06,7555.06 cw(c5859.08,7555.06) U1.223@5854.12,7560.02 ; U1.223@5852.06,7585.69 5852.06,7501.06 5800,7449 5800,7019 5876,6943 6380,6943 6417.02,6905.98 6417.02,6748.98 6491,6675 6776,6675 v1(6840,6739) ; U4.36@6414.97,6798.48 cw(c6410.01,6793.52) 6417.03,6793.52 ; U4.36@6414.97,6869.52 ccw(c6410.01,6874.48) 6417.03,6874.48 ; 6417.02,6793.52 cw(c6424.04,6793.52) U4.36@6419.08,6798.48 ; 6417.02,6874.48 ccw(c6424.04,6874.48) U4.36@6419.08,6869.52 ; v1@6835,6739 cw(c6822.93,6739) 6831.46,6730.46 cw(c6840,6721.93) v1@6840,6734
  BottomLayer w6: v1@6840,6734 cw(c6840,6721.93) 6848.54,6730.46 cw(c6857.07,6739) v1@6845,6739 ; v1(6840,6739) 6917,6662 7221,6662 7333,6774 7387,6774 7487,6874 R69.8@7555.84,6874 ; R69.8@7543.1,6869.76 ccw(c7532.86,6859.51) 7532.86,6874 ccw(c7532.86,6888.49) R69.8@7543.1,6878.24
ED20: R70.6 U1.222 U4.37 | length 2833.7
  TopLayer w6: U1.222@5830.32,7560.02 cw(c5825.36,7555.06) 5832.38,7555.06 cw(c5839.39,7555.06) U1.222@5834.43,7560.02 ; U1.222@5832.38,7585.69 5832.38,7508.38 5783,7459 5783,7004 5858,6929 6366,6929 6397.34,6897.66 6397.34,6735.66 6476,6657 6797,6657 v1(6880,6740) ; U4.37@6395.29,6798.48 cw(c6390.33,6793.52) 6397.34,6793.52 cw(c6404.35,6793.52) U4.37@6399.39,6798.48 ; U4.37@6395.29,6869.52 ccw(c6390.33,6874.48) 6397.34,6874.48 ccw(c6404.35,6874.48) U4.37@6399.39,6869.52 ; v1@6875,6740 cw(c6862.93,6740) 6871.46,6731.46 cw(c6880,6722.93) v1@6880,6735
  BottomLayer w6: v1(6880,6740) 7182,6740 7281,6839 7343,6839 7466,6962 R70.6@7555.84,6962 ; v1@6883.54,6736.46 cw(c6892.07,6727.93) 6892.07,6740 cw(c6892.07,6752.07) v1@6883.54,6743.54 ; R70.6@7543.1,6957.76 ccw(c7532.86,6947.51) 7532.86,6962 ccw(c7532.86,6976.49) R70.6@7543.1,6966.24
ED21: R70.5 U1.219 U4.39 | length 2834.8
  TopLayer w6: U1.219@5771.27,7560.02 cw(c5766.31,7555.06) 5773.32,7555.06 cw(c5780.34,7555.06) U1.219@5775.38,7560.02 ; U1.219@5773.32,7585.69 5773.32,7471.32 5764,7462 5764,6998 5847,6915 6340,6915 6357.97,6897.03 6357.97,6746.03 6467,6637 6804,6637 6870,6703 6883,6703 v1(6902,6722) ; U4.39@6355.92,6798.48 cw(c6350.96,6793.52) 6357.97,6793.52 cw(c6364.98,6793.52) U4.39@6360.02,6798.48 ; U4.39@6355.92,6869.52 ccw(c6350.96,6874.48) 6357.97,6874.48 ccw(c6364.98,6874.48) U4.39@6360.02,6869.52 ; v1@6897,6722 cw(c6884.93,6722) 6893.46,6713.46 cw(c6902,6704.93) v1@6902,6717
  BottomLayer w6: v1(6902,6722) 7190,6722 7292,6824 7354,6824 7456,6926 R70.5@7555.84,6926 ; v1@6905.54,6718.46 cw(c6914.07,6709.93) 6914.07,6722 cw(c6914.07,6734.07) v1@6905.54,6725.54 ; R70.5@7543.1,6921.76 ccw(c7532.86,6911.51) 7532.86,6926 ccw(c7532.86,6940.49) R70.5@7543.1,6930.24
ED22: R33.6 U1.218 U4.40 | length 2923.1
  TopLayer w6: U1.218@5751.58,7560.02 cw(c5746.62,7555.06) 5753.64,7555.06 cw(c5760.65,7555.06) U1.218@5755.69,7560.02 ; U1.218@5753.64,7585.69 5753.64,7492.64 5745,7484 5745,6992 5836,6901 6326,6901 6338.28,6888.72 6338.28,6735.72 6456,6618 6809,6618 6875,6684 6904,6684 v1(6924,6704) ; U4.40@6336.23,6798.48 cw(c6331.27,6793.52) 6338.28,6793.52 cw(c6345.3,6793.52) U4.40@6340.34,6798.48 ; U4.40@6336.23,6869.52 ccw(c6331.27,6874.48) 6338.28,6874.48 ccw(c6345.3,6874.48) U4.40@6340.34,6869.52 ; v1@6919,6704 cw(c6906.93,6704) 6915.46,6695.46 cw(c6924,6686.93) v1@6924,6699 ; v1(7464,6905) 7512,6953 R33.6@7555.84,6953 ; v1@7464,6910 ccw(c7464,6922.07) 7472.54,6913.54 ccw(c7481.07,6905) v1@7469,6905 ; R33.6@7543.1,6948.76 ccw(c7532.86,6938.51) 7532.86,6953 ccw(c7532.86,6967.49) R33.6@7543.1,6957.24
  BottomLayer w6: v1(6924,6704) 7200,6704 7302,6806 7365,6806 v1(7464,6905) ; v1@6927.54,6700.46 cw(c6936.07,6691.93) 6936.07,6704 cw(c6936.07,6716.07) v1@6927.54,6707.54 ; v1@7459,6905 cw(c7446.93,6905) 7455.46,6896.46 cw(c7464,6887.93) v1@7464,6900
ED23: R69.6 U1.217 U4.42 | length 2919.1
  TopLayer w6: U1.217@5731.9,7560.02 cw(c5726.94,7555.06) 5733.95,7555.06 cw(c5740.97,7555.06) U1.217@5736.01,7560.02 ; U1.217@5733.95,7585.69 5733.95,7491.95 5726,7484 5726,6981 5818,6889 6285,6889 6298.91,6875.09 6298.91,6731.09 6429,6601 6821,6601 v1(6886,6666) ; 6288.57,6885.43 cw(c6270.6,6867.46) U4.42@6296.01,6867.46 ; U4.42@6296.86,6798.48 cw(c6291.9,6793.52) 6298.91,6793.52 cw(c6305.93,6793.52) U4.42@6300.97,6798.48 ; U4.42@6296.86,6869.52 ccw(c6291.9,6874.48) 6298.91,6874.48 ccw(c6305.93,6874.48) U4.42@6300.97,6869.52 ; 6298.81,6875.19 cw(c6291.08,6867.46) U4.42@6302.01,6867.46 ; v1@6881,6666 cw(c6868.93,6666) 6877.46,6657.46 cw(c6886,6648.93) v1@6886,6661
  BottomLayer w6: v1@6886,6661 cw(c6886,6648.93) 6894.54,6657.46 cw(c6903.07,6666) v1@6891,6666 ; v1(6886,6666) 6927,6625 7240,6625 7356,6741 7407,6741 7468,6802 R69.6@7555.84,6802 ; R69.6@7543.1,6797.76 ccw(c7532.86,6787.51) 7532.86,6802 ccw(c7532.86,6816.49) R69.6@7543.1,6806.24
ED24: R33.7 U1.216 U4.45 | length 3503.3
  TopLayer w6: U1.216@5712.21,7560.02 cw(c5707.25,7555.06) 5714.27,7555.06 cw(c5721.28,7555.06) U1.216@5716.32,7560.02 ; U1.216@5714.27,7585.69 5714.27,7492.27 5633,7411 5633,6573 5891,6315 6291,6315 6298.91,6322.91 ; 6294.81,6318.81 ccw(c6288.59,6325.03) U4.45@6296.35,6329.17 ; U4.45@6296.86,6399.52 ccw(c6291.9,6404.48) 6298.91,6404.48 ccw(c6305.93,6404.48) U4.45@6300.97,6399.52 ; U4.45@6298.91,6364 6298.91,6457.91 6424,6583 6829,6583 6892,6646 6904,6646 v1(6944,6686) ; 6300.54,6324.54 ccw(c6296.06,6329.01) U4.45@6301.65,6331.99 ; v1@6939,6686 cw(c6926.93,6686) 6935.46,6677.46 cw(c6944,6668.93) v1@6944,6681 ; v1(7492,6898) 7511,6917 R33.7@7555.84,6917 ; v1@7492,6903 ccw(c7492,6915.07) 7500.54,6906.54 ccw(c7509.07,6898) v1@7497,6898 ; R33.7@7543.1,6912.76 ccw(c7532.86,6902.51) 7532.86,6917 ccw(c7532.86,6931.49) R33.7@7543.1,6921.24
  BottomLayer w6: v1(6944,6686) 7209,6686 7313,6790 7384,6790 v1(7492,6898) ; v1@6947.54,6682.46 cw(c6956.07,6673.93) 6956.07,6686 cw(c6956.07,6698.07) v1@6947.54,6689.54 ; v1@7487,6898 cw(c7474.93,6898) 7483.46,6889.46 cw(c7492,6880.93) v1@7492,6893
ED25: R69.7 U1.215 U4.47 | length 3505.2
  TopLayer w6: U1.215@5692.53,7560.02 cw(c5687.57,7555.06) 5694.58,7555.06 cw(c5701.6,7555.06) U1.215@5696.64,7560.02 ; U1.215@5694.58,7585.69 5694.58,7495.58 5617,7418 5617,6567 5881,6303 6327,6303 6338.28,6314.28 6338.28,6469.28 6435.88,6566.88 6834.88,6566.88 6893,6625 6965.12,6625 v1(6983.12,6643) ; U4.47@6336.23,6328.48 cw(c6331.27,6323.52) 6338.28,6323.52 cw(c6345.3,6323.52) U4.47@6340.34,6328.48 ; U4.47@6336.23,6399.52 ccw(c6331.27,6404.48) 6338.28,6404.48 ccw(c6345.3,6404.48) U4.47@6340.34,6399.52 ; v1@6978.12,6643 cw(c6966.05,6643) 6974.59,6634.46 cw(c6983.12,6625.93) v1@6983.12,6638
  BottomLayer w6: v1(6983.12,6643) 7233,6643 7345,6755 7392,6755 7475,6838 R69.7@7555.84,6838 ; v1@6986.66,6639.46 cw(c6995.19,6630.93) 6995.19,6643 cw(c6995.19,6655.07) v1@6986.66,6646.54 ; R69.7@7543.1,6833.76 ccw(c7532.86,6823.51) 7532.86,6838 ccw(c7532.86,6852.49) R69.7@7543.1,6842.24
ED26: R33.8 U1.214 U4.48 | length 3623.4
  TopLayer w6: U1.214@5672.84,7560.02 cw(c5667.88,7555.06) 5674.9,7555.06 cw(c5681.91,7555.06) U1.214@5676.95,7560.02 ; U1.214@5674.9,7585.69 5674.9,7500.9 5601,7427 5601,6556 5866,6291 6341,6291 6357.97,6307.97 6357.97,6466.97 6442,6551 6843,6551 6897,6605 v1(7023,6605) ; U4.48@6355.92,6328.48 cw(c6350.96,6323.52) 6357.97,6323.52 cw(c6364.98,6323.52) U4.48@6360.02,6328.48 ; U4.48@6355.92,6399.52 ccw(c6350.96,6404.48) 6357.97,6404.48 ccw(c6364.98,6404.48) U4.48@6360.02,6399.52 ; v1@7019.46,6601.46 ccw(c7010.93,6592.93) 7010.93,6605 ccw(c7010.93,6617.07) v1@7019.46,6608.54 ; v1@7440.46,6746.54 ccw(c7431.93,6755.07) 7444,6755.07 ccw(c7456.07,6755.07) v1@7447.54,6746.54 ; v1(7444,6743) 7444,6793 7532,6881 R33.8@7555.84,6881 ; R33.8@7543.1,6876.76 ccw(c7532.86,6866.51) 7532.86,6881 ccw(c7532.86,6895.49) R33.8@7543.1,6885.24
  BottomLayer w6: v1(7023,6605) 7249,6605 7372,6728 7429,6728 v1(7444,6743) ; v1@7026.54,6601.46 cw(c7035.07,6592.93) 7035.07,6605 cw(c7035.07,6617.07) v1@7026.54,6608.54 ; v1@7439,6743 cw(c7426.93,6743) 7435.46,6734.46 cw(c7444,6725.93) v1@7444,6738
ED27: R69.5 U1.213 U4.50 | length 3541.1
  TopLayer w6: U1.213@5653.16,7560.02 cw(c5648.2,7555.06) 5655.21,7555.06 cw(c5662.23,7555.06) U1.213@5657.27,7560.02 ; U1.213@5655.21,7585.69 5655.21,7507.21 5586,7438 5586,6551 5858,6279 6365.34,6279 6397.34,6311 6397.34,6481.34 6450,6534 6848,6534 6898,6584 v1(7043,6584) ; U4.50@6395.29,6328.48 cw(c6390.33,6323.52) 6397.34,6323.52 cw(c6404.35,6323.52) U4.50@6399.39,6328.48 ; U4.50@6395.29,6399.52 ccw(c6390.33,6404.48) 6397.34,6404.48 ccw(c6404.35,6404.48) U4.50@6399.39,6399.52 ; v1@7039.46,6580.46 ccw(c7030.93,6571.93) 7030.93,6584 ccw(c7030.93,6596.07) v1@7039.46,6587.54
  BottomLayer w6: v1(7043,6584) 7255,6584 7384,6713 7466,6713 7519,6766 R69.5@7555.84,6766 ; v1@7046.54,6580.46 cw(c7055.07,6571.93) 7055.07,6584 cw(c7055.07,6596.07) v1@7046.54,6587.54 ; R69.5@7543.1,6761.76 ccw(c7532.86,6751.51) 7532.86,6766 ccw(c7532.86,6780.49) R69.5@7543.1,6770.24
ED28: R32.6 U1.208 U4.51 | length 3615.7
  TopLayer w6: U1.208@5554.73,7560.02 cw(c5549.77,7555.06) 5556.79,7555.06 cw(c5563.8,7555.06) U1.208@5558.84,7560.02 ; U1.208@5556.79,7585.69 5556.79,7450.21 5572,7435 5572,6547 5852,6267 6371,6267 6417.02,6313.02 6417.02,6466.02 6467,6516 6854,6516 6900,6562 v1(7064,6562) ; U4.51@6414.97,6328.48 cw(c6410.01,6323.52) 6417.03,6323.52 ; U4.51@6414.97,6399.52 ccw(c6410.01,6404.48) 6417.03,6404.48 ; 6417.02,6323.52 cw(c6424.04,6323.52) U4.51@6419.08,6328.48 ; 6417.02,6404.48 ccw(c6424.04,6404.48) U4.51@6419.08,6399.52 ; v1@7060.46,6558.46 ccw(c7051.93,6549.93) 7051.93,6562 ccw(c7051.93,6574.07) v1@7060.46,6565.54 ; v1(7463,6690) 7479,6706 7479,6732 7540,6793 R32.6@7555.84,6793 ; v1@7463,6695 ccw(c7463,6707.07) 7471.54,6698.54 ccw(c7480.07,6690) v1@7468,6690 ; 7524.57,6777.57 cw(c7547.34,6754.79) R32.6@7547.34,6787 ; 7534.81,6787.81 cw(c7547.34,6775.27) R32.6@7547.34,6793
  BottomLayer w6: v1(7064,6562) 7260,6562 7388,6690 v1(7463,6690) ; v1@7067.54,6558.46 cw(c7076.07,6549.93) 7076.07,6562 cw(c7076.07,6574.07) v1@7067.54,6565.54 ; v1@7459.46,6686.46 ccw(c7450.93,6677.93) 7450.93,6690 ccw(c7450.93,6702.07) v1@7459.46,6693.54
ED29: R32.5 U1.207 U4.53 | length 3664.9
  TopLayer w6: U1.207@5535.05,7560.02 cw(c5530.09,7555.06) 5537.1,7555.06 cw(c5544.12,7555.06) U1.207@5539.16,7560.02 ; U1.207@5537.1,7585.69 5537.1,7433.9 5556,7415 5556,6541 5843,6254 6388,6254 6456.4,6322.4 6456.4,6442.4 6514,6500 6860,6500 6902,6542 v1(7083,6542) ; 6445.68,6311.68 ccw(c6426.82,6330.54) U4.53@6453.49,6330.54 ; U4.53@6454.34,6328.48 cw(c6449.38,6323.52) 6456.4,6323.52 cw(c6463.41,6323.52) U4.53@6458.45,6328.48 ; U4.53@6454.34,6399.52 ccw(c6449.38,6404.48) 6456.4,6404.48 ccw(c6463.41,6404.48) U4.53@6458.45,6399.52 ; 6455.92,6321.92 ccw(c6447.31,6330.54) U4.53@6459.49,6330.54 ; v1@7079.46,6538.46 ccw(c7070.93,6529.93) 7070.93,6542 ccw(c7070.93,6554.07) v1@7079.46,6545.54 ; v1(7408.12,6668.12) 7465,6725 7465,6766 7528,6829 R32.5@7555.84,6829 ; v1@7408.12,6673.12 ccw(c7408.12,6685.19) 7416.65,6676.65 ccw(c7425.19,6668.12) v1@7413.12,6668.12 ; R32.5@7543.1,6824.76 ccw(c7532.86,6814.51) 7532.86,6829 ccw(c7532.86,6843.49) R32.5@7543.1,6833.24
  BottomLayer w6: v1(7083,6542) 7281,6542 ; v1@7086.54,6538.46 cw(c7095.07,6529.93) 7095.07,6542 cw(c7095.07,6554.07) v1@7086.54,6545.54 ; 7282,6542 v1(7408.12,6668.12) ; v1@7403.12,6668.12 cw(c7391.05,6668.12) 7399.58,6659.58 cw(c7408.12,6651.05) v1@7408.12,6663.12
ED30: R32.8 U1.206 U4.54 | length 3594.9
  TopLayer w6: U1.206@5515.36,7560.02 cw(c5510.4,7555.06) 5517.42,7555.06 cw(c5524.43,7555.06) U1.206@5519.47,7560.02 ; U1.206@5517.42,7585.69 5517.42,7424.58 5542,7400 5542,6535 5836,6241 6404,6241 6476.08,6313.08 6476.08,6429 6530.08,6483 6866,6483 6908,6525 v1(7109,6525) ; U4.54@6474.03,6328.48 cw(c6469.07,6323.52) 6476.08,6323.52 cw(c6483.09,6323.52) U4.54@6478.13,6328.48 ; U4.54@6474.03,6399.52 ccw(c6469.07,6404.48) 6476.08,6404.48 ccw(c6483.09,6404.48) U4.54@6478.13,6399.52 ; v1@7105.46,6521.46 ccw(c7096.93,6512.93) 7096.93,6525 ccw(c7096.93,6537.07) v1@7105.46,6528.54 ; v1(7522,6721) R32.8@7555.84,6721 ; v1@7525.54,6717.46 cw(c7534.07,6708.93) 7534.07,6721 cw(c7534.07,6733.07) v1@7525.54,6724.54 ; R32.8@7543.1,6716.76 ccw(c7532.86,6706.51) 7532.86,6721 ccw(c7532.86,6735.49) R32.8@7543.1,6725.24
  BottomLayer w6: v1(7109,6525) 7326,6525 v1(7522,6721) ; v1@7112.54,6521.46 cw(c7121.07,6512.93) 7121.07,6525 cw(c7121.07,6537.07) v1@7112.54,6528.54 ; v1@7517,6721 cw(c7504.93,6721) 7513.46,6712.46 cw(c7522,6703.93) v1@7522,6716
ED31: R32.7 U1.203 U4.56 | length 3706.6
  TopLayer w6: U1.203@5456.31,7560.02 cw(c5451.35,7555.06) 5458.36,7555.06 cw(c5465.38,7555.06) U1.203@5460.42,7560.02 ; U1.203@5458.36,7585.69 5458.36,7457.64 5528,7388 5528,6525 5825,6228 6436,6228 6515.45,6307.45 6515.45,6439.45 6543,6467 6883,6467 v1(6920,6504) ; U4.56@6513.4,6328.48 cw(c6508.44,6323.52) 6515.45,6323.52 cw(c6522.46,6323.52) U4.56@6517.5,6328.48 ; U4.56@6513.4,6399.52 ccw(c6508.44,6404.48) 6515.45,6404.48 ccw(c6522.46,6404.48) U4.56@6517.5,6399.52 ; v1@6915,6504 cw(c6902.93,6504) 6911.46,6495.46 cw(c6920,6486.93) v1@6920,6499 ; v1@7488.46,6658.54 ccw(c7479.93,6667.07) 7492,6667.07 ccw(c7504.07,6667.07) v1@7495.54,6658.54 ; v1(7492,6655) 7492,6720 7529,6757 R32.7@7555.84,6757 ; R32.7@7543.1,6752.76 ccw(c7532.86,6742.51) 7532.86,6757 ccw(c7532.86,6771.49) R32.7@7543.1,6761.24
  BottomLayer w6: v1(6920,6504) 7341,6504 v1(7492,6655) ; v1@6923.54,6500.46 cw(c6932.07,6491.93) 6932.07,6504 cw(c6932.07,6516.07) v1@6923.54,6507.54 ; v1@7487,6655 cw(c7474.93,6655) 7483.46,6646.46 cw(c7492,6637.93) v1@7492,6650
EMU0: J2.13 U11.A15 | length 1301.3
  TopLayer w6: U11.A15@8414.82,6834 8414.82,6634.18 8651,6398 8721,6398 8828,6291 8828,6266 8863,6231 9029,6231 J2.13@9080,6180 ; J2.13@9053.47,6180 ccw(c8989.43,6180) 9034.71,6225.29 ccw(c9080,6270.57) J2.13@9080,6206.53 ; J2.13@9059.47,6180 ccw(c9009.91,6180) 9044.96,6215.04 ccw(c9080,6250.09) J2.13@9080,6200.53 ; J2.13@9065.47,6180 ccw(c9030.4,6180) 9055.2,6204.8 ccw(c9080,6229.6) J2.13@9080,6194.53
EMU1: J2.14 U11.C14 | length 1307.4
  TopLayer w6: U11.C14@8454.19,6912.74 8434,6892.55 8434,6644 8659,6419 8740,6419 8822,6337 9023,6337 J2.14@9080,6280 ; J2.14@9053.47,6280 ccw(c8989.43,6280) 9034.71,6325.29 ccw(c9080,6370.57) J2.14@9080,6306.53 ; J2.14@9059.47,6280 ccw(c9009.91,6280) 9044.96,6315.04 ccw(c9080,6350.09) J2.14@9080,6300.53 ; J2.14@9065.47,6280 ccw(c9030.4,6280) 9055.2,6304.8 ccw(c9080,6329.6) J2.14@9080,6294.53
FPGA_ASDO: JP11.9 U1.37 U19.5 | length 1257
  TopLayer w6: U1.37@6274.31,8381.95 6362.05,8381.95 v1(6466,8278) ; U1.37@6299.98,8379.9 cw(c6304.94,8374.94) 6304.94,8381.95 cw(c6304.94,8388.97) U1.37@6299.98,8384.01 ; v1@6461,8278 ccw(c6448.93,8278) 6457.46,8286.54 ccw(c6466,8295.07) v1@6466,8283
  BottomLayer w6: v1(6466,8278) 6686,8278 6705,8259 6705,8147 6620,8062 JP11.9@6620,7900 ; v1@6469.54,8274.46 cw(c6478.07,8265.93) 6478.07,8278 cw(c6478.07,8290.07) v1@6469.54,8281.54 ; JP11.9@6600.2,7919.8 ccw(c6552.4,7967.6) 6620,7967.6 ccw(c6687.6,7967.6) JP11.9@6639.8,7919.8 ; JP11.9@6604.44,7915.56 ccw(c6566.89,7953.11) 6620,7953.11 ccw(c6673.11,7953.11) JP11.9@6635.56,7915.56 ; JP11.9@6608.69,7911.31 ccw(c6581.37,7938.63) 6620,7938.63 ccw(c6658.63,7938.63) JP11.9@6631.31,7911.31 ; 6686.32,8277.68 cw(c6662.5,8253.86) U19.5@6696.19,8253.86 ; 6696.57,8267.43 cw(c6682.99,8253.86) U19.5@6702.19,8253.86 ; U19.5@6698.77,8184.64 cw(c6683.73,8169.59) 6705,8169.59 cw(c6726.27,8169.59) U19.5@6711.23,8184.64 ; U19.5@6698.74,8265.26 ccw(c6705,8271.53) U19.5@6705,8262.67
FPGA_IO41: JP12.1 U1.41 | length 789.7
  TopLayer w6: U1.41@6274.31,8460.69 6623.69,8460.69 6760,8597 JP12.1@6760,8600 ; U1.41@6299.98,8458.64 cw(c6304.94,8453.68) 6304.94,8460.69 cw(c6304.94,8467.71) U1.41@6299.98,8462.75 ; 6712.59,8549.59 ccw(c6662.19,8600) JP12.1@6733.47,8600 ; 6719.84,8556.84 cw(c6760,8516.67) JP12.1@6760,8573.47 ; 6722.84,8559.84 ccw(c6682.67,8600) JP12.1@6739.47,8600 ; 6730.08,8567.08 cw(c6760,8537.16) JP12.1@6760,8579.47 ; 6733.08,8570.08 ccw(c6703.16,8600) JP12.1@6745.47,8600 ; JP12.1@6740.32,8577.32 cw(c6760,8557.64) JP12.1@6760,8585.47
FPGA_IO42: JP12.2 U1.42 | length 602.9
  TopLayer w6: U1.42@6274.31,8480.38 6592.38,8480.38 6660,8548 ; U1.42@6299.98,8478.32 cw(c6304.94,8473.36) 6304.94,8480.38 cw(c6304.94,8487.39) U1.42@6299.98,8482.43 ; JP12.2@6644.43,8578.52 cw(c6622.3,8548) 6660,8548 ; JP12.2@6647.95,8583.38 cw(c6630.83,8559.76) 6660,8559.76 cw(c6689.17,8559.76) JP12.2@6672.05,8583.38 ; JP12.2@6660,8600 6660,8548 ; JP12.2@6675.57,8578.52 ccw(c6697.7,8548) 6660,8548
FPGA_IO43: JP12.3 U1.43 | length 856.4
  TopLayer w6: U1.43@6274.31,8500.06 6569.06,8500.06 6605,8536 6605,8610 6643,8648 6708,8648 JP12.3@6760,8700 ; U1.43@6299.98,8498.01 cw(c6304.94,8493.05) 6304.94,8500.06 cw(c6304.94,8507.08) U1.43@6299.98,8502.12 ; JP12.3@6733.47,8700 cw(c6669.43,8700) 6714.71,8654.71 cw(c6760,8609.43) JP12.3@6760,8673.47 ; JP12.3@6739.47,8700 cw(c6689.91,8700) 6724.96,8664.96 cw(c6760,8629.91) JP12.3@6760,8679.47 ; JP12.3@6745.47,8700 cw(c6710.4,8700) 6735.2,8675.2 cw(c6760,8650.4) JP12.3@6760,8685.47
FPGA_IO44: JP12.4 U1.44 | length 751.8
  TopLayer w6: U1.44@6274.31,8519.75 6559.75,8519.75 6583,8543 6583,8623 JP12.4@6660,8700 ; U1.44@6299.98,8517.69 cw(c6304.94,8512.73) 6304.94,8519.75 cw(c6304.94,8526.76) U1.44@6299.98,8521.8 ; JP12.4@6633.47,8700 cw(c6569.43,8700) 6614.71,8654.71 cw(c6660,8609.43) JP12.4@6660,8673.47 ; JP12.4@6639.47,8700 cw(c6589.91,8700) 6624.96,8664.96 cw(c6660,8629.91) JP12.4@6660,8679.47 ; JP12.4@6645.47,8700 cw(c6610.4,8700) 6635.2,8675.2 cw(c6660,8650.4) JP12.4@6660,8685.47
FPGA_NCSO: JP11.8 U1.24 U19.1 | length 1521.4
  TopLayer w6: U1.24@6276.35,8124 U1.24@6274.31,8126.05 6472.95,8126.05 6558,8041 6558,7877 6586,7849 6671,7849 JP11.8@6720,7800 ; U1.24@6299.98,8123.99 cw(c6304.94,8119.03) 6304.94,8126.05 cw(c6304.94,8133.06) U1.24@6299.98,8128.1 ; JP11.8@6692,7800 ccw(c6624.4,7800) 6672.2,7847.8 ccw(c6720,7895.6) JP11.8@6720,7828 ; JP11.8@6698,7800 ccw(c6644.89,7800) 6682.44,7837.56 ccw(c6720,7875.11) JP11.8@6720,7822 ; JP11.8@6704,7800 ccw(c6665.37,7800) 6692.69,7827.31 ccw(c6720,7854.63) JP11.8@6720,7816
  BottomLayer w6: JP11.8@6720,7800 6773,7853 6844,7853 6873,7882 6873,7999.64 U19.1@6855,8017.64 ; JP11.8@6720,7816 ccw(c6720,7854.63) 6747.31,7827.31 ccw(c6774.63,7800) JP11.8@6736,7800 ; JP11.8@6720,7822 ccw(c6720,7875.11) 6757.56,7837.56 ccw(c6795.11,7800) JP11.8@6742,7800 ; JP11.8@6720,7828 ccw(c6720,7895.6) 6767.8,7847.8 ccw(c6815.6,7800) JP11.8@6748,7800
FPGA_PLLOUT: R75.1 U1.39 | length 1686.1
  TopLayer w6: U1.39@6274.31,8421.32 6318.68,8421.32 v1(6328,8412) ; U1.39@6299.98,8419.27 cw(c6304.94,8414.31) 6304.94,8421.32 cw(c6304.94,8428.34) U1.39@6299.98,8423.38 ; v1@6323,8412 ccw(c6310.93,8412) 6319.46,8420.54 ccw(c6328,8429.07) v1@6328,8417
  BottomLayer w6: v1@6328,8407 cw(c6328,8399.76) 6333.12,8404.88 ; v1(6328,8412) 6328,8410 6421,8317 6907,8317 7144,8080 7144,7795 7225,7714 R75.1@7346.54,7714 ; v1@6333,8412 ccw(c6349.9,8412) 6337.95,8400.05 ; R75.1@7332.77,7702.2 ccw(c7304.29,7673.72) 7304.29,7714 ccw(c7304.29,7754.28) R75.1@7332.77,7725.8 ; R75.1@7337.01,7706.44 ccw(c7318.77,7688.2) 7318.77,7714 ccw(c7318.77,7739.8) R75.1@7337.01,7721.56
GCLK1: R23.2 U1.29 | length 266
  TopLayer w12: U1.29@6274.31,8224.47 6482.06,8224.47 R23.2@6486.54,8220 ; 6440.73,8224.47 cw(c6440.73,8176.16) R23.2@6474.89,8210.32 ; 6462.33,8224.47 ccw(c6462.33,8242.24) R23.2@6474.89,8229.68
GGND: FB1.1 FB3.1 FB5.1 pad.0 pad.2@4140,6217 pad.10 pad.11 pad.12 | length 2792.6
  TopLayer w12: FB1.1@4573.32,6097.89 cw(c4549.96,6074.53) 4583,6074.53 cw(c4616.04,6074.53) FB1.1@4592.68,6097.89 ; pad.10@4578.76,6039.24 ccw(c4568.51,6049.49) 4583,6049.49 ccw(c4597.49,6049.49) pad.10@4587.24,6039.24 ; v3(4583,6035) FB1.1@4583,6109.54 ccw(c4646.5,6109.53) pad.10@4619.14,6052.23 ; pad.10@4583,6052.45 ccw(c4619.24,6052.45) pad.10@4603.63,6019.74 ; 4583,6071.48 ccw(c4628.33,6071.48) pad.10@4608.8,6030.57 ; FB1.1@4583,6090.51 ccw(c4637.41,6090.51) pad.10@4613.97,6041.4 ; pad.10@5183,6046 5183,6075 5197,6089 5458,6089 pad.11@5496,6051 ; 5454.32,6092.68 cw(c5415.14,6053.51) pad.11@5467.88,6036.53 ; 5468.21,6078.79 cw(c5436.16,6046.74) pad.11@5479.3,6032.86 ; 5482.09,6064.91 cw(c5457.17,6039.98) pad.11@5490.72,6029.18 ; FB3.1@7470.32,6094.89 cw(c7446.96,6071.53) 7480,6071.53 cw(c7513.04,6071.53) FB3.1@7489.68,6094.89 ; pad.11@7475.76,6037.24 ccw(c7465.51,6047.49) 7480,6047.49 ccw(c7494.49,6047.49) pad.11@7484.24,6037.24 ; v3(7480,6033) FB3.1@7480,6106.54 8727.46,6106.54 pad.12@8801,6033 ; FB3.1@7489.68,6096.86 cw(c7513.04,6073.5) 7513.04,6106.54 cw(c7513.04,6139.57) FB3.1@7489.68,6116.21 ; 8725.98,6108.02 cw(c8653.68,6035.71) pad.12@8755.63,6027.88 ; 8744.44,6089.56 cw(c8687.95,6033.08) pad.12@8767.6,6026.96 ; 8762.89,6071.11 cw(c8722.22,6030.45) pad.12@8779.56,6026.04 ; FB5.1@9323.79,6090.32 cw(c9300.43,6066.96) 9333.46,6066.96 cw(c9366.5,6066.96) FB5.1@9343.14,6090.32 ; pad.12@9329.22,6030.78 ccw(c9318.98,6041.02) 9333.46,6041.02 ccw(c9347.95,6041.02) pad.12@9337.71,6030.78 ; v3(9333.46,6026.54) FB5.1@9333.46,6100
  other v2: 10041,6014 9046,6021 9735,6024 6211,6025 4245,6028 4807,6028 6996,6029 5030,6030 4065,6031 4421,6032 5593,6033 5819,6033 6528,6033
